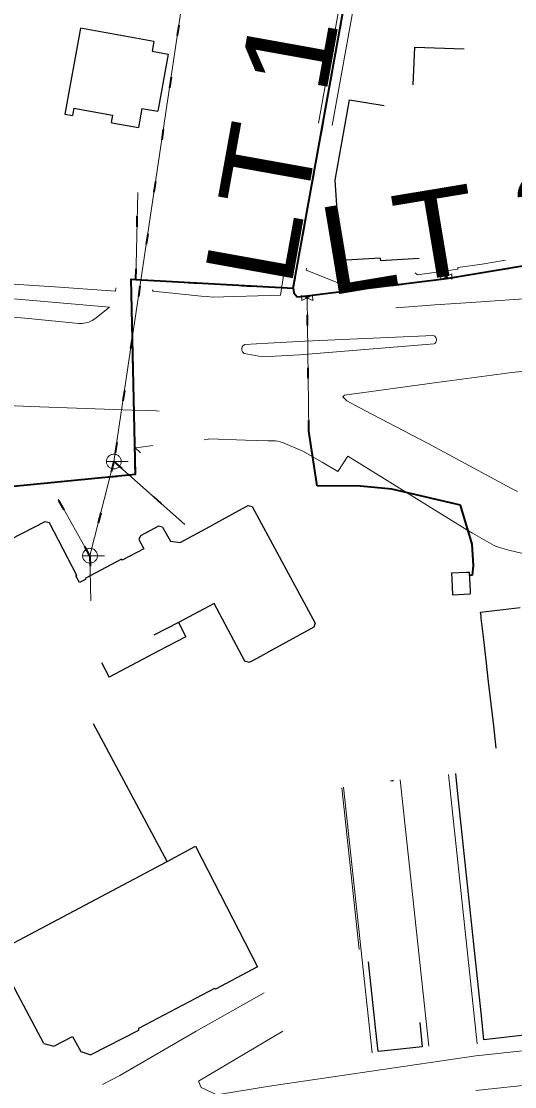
# Model space of a CAD drawing. Extents: x -968691 to -140888, y -1376050 to -879856.
# Drawn here: x -646308.7 to -646241.5, y -1062477.8 to -1062332.4 of the extents above; entities that cross this region are included whole.
import ezdxf
from ezdxf.enums import TextEntityAlignment as Align

# ---------------------------------------------------------------- set-up
doc = ezdxf.new("R2010")
doc.units = 0
doc.header["$LTSCALE"] = 4.8
for name, pattern in [('DASH_DOUBLE_DOT', [9.2, 5, -1.2, 0.3, -1.2, 0.3, -1.2]), ('DOTTED', [1.5, 0.3, -1.2]), ('LONG_DASHED', [7.5, 6, -1.5])]:
    doc.linetypes.add(name, pattern=pattern)
doc.layers.add('1', color=7, linetype='Continuous', lineweight=13)

msp = doc.modelspace()

# ---------------------------------------------------------------- linework, layer by layer
at = {"layer": '1'}
for p, q in [((-646262.19, -1062312.54), (-646268.225, -1062346.311)), ((-646260.32, -1062312.875), (-646266.355, -1062346.646)), ((-646286.21, -1062325.82), (-646296.122, -1062392.506)), ((-646293.117, -1062367.659), (-646292.87, -1062355.786)), ((-646273.428, -1062369.796), (-646272.751, -1062365.655)), ((-646269.896, -1062366.408), (-646269.848, -1062366.134)), ((-646265.209, -1062368.251), (-646269.896, -1062366.408)), ((-646254.709, -1062367.032), (-646255.046, -1062366.763)), ((-646249.248, -1062366.235), (-646254.709, -1062367.032)), ((-646312.371, -1062368.109), (-646303.55, -1062368.728)), ((-646312.411, -1062370.102), (-646308.696, -1062370.373)), ((-646303.55, -1062368.728), (-646295.911, -1062369.253)), ((-646290.786, -1062369.268), (-646284.212, -1062369.937)), ((-646282.733, -1062370.071), (-646273.428, -1062369.796)), ((-646269.774, -1062370.176), (-646269.801, -1062369.898)), ((-646308.696, -1062370.373), (-646296.712, -1062371.438)), ((-646298.709, -1062373.016), (-646296.712, -1062371.438)), ((-646269.53, -1062388.34), (-646269.774, -1062370.176)), ((-646247.414, -1062370.785), (-646238.073, -1062370.161)), ((-646314.855, -1062372.333), (-646307.745, -1062372.993)), ((-646307.745, -1062372.993), (-646300.902, -1062373.653)), ((-646270.09, -1062376.07), (-646252.56, -1062375.28)), ((-646278.29, -1062376.55), (-646275.09, -1062376.36)), ((-646275.09, -1062376.36), (-646270.09, -1062376.07)), ((-646252.47, -1062376.45), (-646270.75, -1062377.94)), ((-646275.86, -1062378.21), (-646278.34, -1062377.77)), ((-646270.75, -1062377.94), (-646275.86, -1062378.21)), ((-646252.076, -1062381.734), (-646264.679, -1062383.451)), ((-646306.24, -1062385.02), (-646319.42, -1062384.54)), ((-646264.679, -1062383.451), (-646264.927, -1062383.672)), ((-646293.624, -1062385.473), (-646306.24, -1062385.02)), ((-646289.937, -1062385.61), (-646290.37, -1062385.59)), ((-646261.889, -1062385.53), (-646253.371, -1062390.016)), ((-646268.43, -1062395.82), (-646269.53, -1062388.34)), ((-646283.208, -1062389.43), (-646283.83, -1062389.547)), ((-646275.105, -1062389.666), (-646278.162, -1062389.562)), ((-646253.371, -1062390.016), (-646241.928, -1062396.191)), ((-646265.578, -1062393.878), (-646264.212, -1062391.745)), ((-646250.506, -1062400.256), (-646264.212, -1062391.745)), ((-646296.122, -1062392.506), (-646299.377, -1062405.352)), ((-646297.13, -1062392.506), (-646294.153, -1062392.506)), ((-646296.122, -1062392.506), (-646286.466, -1062401.077)), ((-646262.49, -1062395.85), (-646268.43, -1062395.82)), ((-646258.22, -1062396.28), (-646262.49, -1062395.85)), ((-646248.85, -1062398.46), (-646258.22, -1062396.28)), ((-646299.377, -1062405.352), (-646303.731, -1062397.633)), ((-646247.27, -1062403.79), (-646248.85, -1062398.46)), ((-646300.385, -1062405.352), (-646297.408, -1062405.352)), ((-646299.377, -1062405.352), (-646299.27, -1062411.52)), ((-646247.22, -1062408.02), (-646247.686, -1062408.036)), ((-646250.514, -1062435.191), (-646246.61, -1062471.95)), ((-646260.895, -1062473.209), (-646264.803, -1062436.925)), ((-646253.194, -1062472.283), (-646257.089, -1062435.938)), ((-646265.055, -1062437.019), (-646262.682, -1062459.081)), ((-646275.652, -1062465.012), (-646284.904, -1062470.225)), ((-646191.32, -1062467.59), (-646246.76, -1062473.59)), ((-646284.904, -1062470.225), (-646295.307, -1062476.3)), ((-646273.072, -1062470.218), (-646284.6, -1062477.07)), ((-646246.8, -1062478.33), (-646190.49, -1062472.19)), ((-646246.76, -1062473.59), (-646275.206, -1062477.789)), ((-646295.307, -1062476.3), (-646297.658, -1062477.513))]:
    msp.add_line(p, q, dxfattribs=at)
at = {"layer": '1', "linetype": 'DOTTED', "lineweight": 40}
for p, q in [((-646271.669, -1062368.865), (-646261.793, -1062314.04)), ((-646286.21, -1062325.82), (-646296.122, -1062392.506)), ((-646293.117, -1062367.659), (-646292.87, -1062355.786)), ((-646269.774, -1062370.176), (-646269.801, -1062369.898)), ((-646269.53, -1062388.34), (-646269.774, -1062370.176)), ((-646296.122, -1062392.506), (-646299.377, -1062405.352)), ((-646296.122, -1062392.506), (-646286.466, -1062401.077)), ((-646299.377, -1062405.352), (-646303.731, -1062397.633)), ((-646299.377, -1062405.352), (-646299.27, -1062411.52))]:
    msp.add_line(p, q, dxfattribs=at)
at = {"layer": '1', "lineweight": 35}
msp.add_line((-646271.669, -1062368.865), (-646261.793, -1062314.04), dxfattribs=at)
at = {"layer": '1', "lineweight": 25}
for p, q in [((-646300.668, -1062333.382), (-646302.8, -1062345.11)), ((-646290.664, -1062335.183), (-646300.668, -1062333.382)), ((-646290.664, -1062335.183), (-646290.904, -1062336.501)), ((-646290.904, -1062336.501), (-646288.72, -1062336.898)), ((-646255.31, -1062341.076), (-646255.08, -1062335.946)), ((-646255.08, -1062335.946), (-646248.39, -1062336.189)), ((-646288.72, -1062336.898), (-646290.14, -1062344.71)), ((-646302.8, -1062345.11), (-646301.76, -1062345.29)), ((-646301.584, -1062344.273), (-646301.76, -1062345.29)), ((-646301.584, -1062344.273), (-646296.32, -1062345.23)), ((-646296.32, -1062345.23), (-646296.48, -1062346.25)), ((-646292.318, -1062344.321), (-646292.78, -1062346.91)), ((-646292.318, -1062344.321), (-646290.14, -1062344.71)), ((-646296.48, -1062346.25), (-646296.104, -1062346.317)), ((-646296.104, -1062346.317), (-646292.78, -1062346.91)), ((-646265.216, -1062365.085), (-646265.961, -1062354.088)), ((-646259.81, -1062364.763), (-646265.216, -1062365.085)), ((-646259.81, -1062364.763), (-646259.79, -1062365.101)), ((-646254.491, -1062364.785), (-646259.79, -1062365.101)), ((-646290.038, -1062401.322), (-646292.502, -1062402.641)), ((-646289.489, -1062401.472), (-646290.038, -1062401.322)), ((-646289.489, -1062401.472), (-646288.42, -1062403.36)), ((-646287.103, -1062403.549), (-646283.535, -1062401.619)), ((-646292.502, -1062402.641), (-646292.713, -1062403.154)), ((-646292.713, -1062403.154), (-646292.043, -1062404.413)), ((-646288.42, -1062403.36), (-646287.103, -1062403.549)), ((-646295.764, -1062406.193), (-646300.054, -1062408.469)), ((-646250.11, -1062407.7), (-646248.068, -1062407.598)), ((-646250.11, -1062407.7), (-646250.065, -1062408.613)), ((-646247.7, -1062407.58), (-646247.653, -1062408.529)), ((-646300.054, -1062408.469), (-646299.991, -1062408.577)), ((-646250.065, -1062408.613), (-646249.962, -1062410.677)), ((-646249.962, -1062410.677), (-646247.552, -1062410.557)), ((-646282.469, -1062411.878), (-646283.796, -1062412.579)), ((-646278.276, -1062419.745), (-646282.469, -1062411.878)), ((-646246.13, -1062413.04), (-646240.719, -1062412.421)), ((-646287.332, -1062414.447), (-646290.657, -1062416.203)), ((-646268.844, -1062415.08), (-646274.584, -1062418.247)), ((-646268.703, -1062414.534), (-646268.844, -1062415.08)), ((-646286.3, -1062416.401), (-646289.97, -1062418.339)), ((-646289.97, -1062418.339), (-646296.744, -1062421.917)), ((-646276.148, -1062419.084), (-646277.327, -1062419.734)), ((-646274.584, -1062418.247), (-646276.148, -1062419.084)), ((-646297.787, -1062419.911), (-646296.744, -1062421.917)), ((-646277.698, -1062419.932), (-646278.276, -1062419.745)), ((-646277.327, -1062419.734), (-646277.698, -1062419.932)), ((-646288.835, -1062447.069), (-646298.9, -1062428.31)), ((-646243.996, -1062431.595), (-646244.346, -1062428.587)), ((-646258.405, -1062436.074), (-646258.157, -1062436.044)), ((-646258.157, -1062436.044), (-646257.984, -1062436.035)), ((-646288.835, -1062447.069), (-646284.979, -1062444.987)), ((-646284.979, -1062444.987), (-646276.523, -1062461.442)), ((-646312.263, -1062459.5), (-646288.835, -1062447.069)), ((-646247.913, -1062450.241), (-646248.23, -1062447.251)), ((-646247.597, -1062453.223), (-646247.913, -1062450.241)), ((-646305.676, -1062471.913), (-646312.263, -1062459.5)), ((-646276.523, -1062461.442), (-646277.298, -1062461.859)), ((-646261.092, -1062463.758), (-646261.412, -1062460.769)), ((-646245.67, -1062471.4), (-646246.014, -1062468.156)), ((-646292.786, -1062470.128), (-646299.262, -1062473.467)), ((-646292.759, -1062469.884), (-646292.786, -1062470.128)), ((-646260.1, -1062473.01), (-646260.453, -1062469.719)), ((-646240.187, -1062470.76), (-646245.67, -1062471.4)), ((-646305.676, -1062471.913), (-646304.318, -1062472.289)), ((-646259.205, -1062472.915), (-646260.1, -1062473.01))]:
    msp.add_line(p, q, dxfattribs=at)
at = {"layer": '1', "linetype": 'LONG_DASHED', "lineweight": 40}
for p, q in [((-646268.43, -1062395.82), (-646269.53, -1062388.34)), ((-646262.49, -1062395.85), (-646268.43, -1062395.82)), ((-646258.22, -1062396.28), (-646262.49, -1062395.85)), ((-646248.85, -1062398.46), (-646258.22, -1062396.28)), ((-646247.27, -1062403.79), (-646248.85, -1062398.46)), ((-646247.22, -1062408.02), (-646247.686, -1062408.036))]:
    msp.add_line(p, q, dxfattribs=at)
at = {"layer": '1', "lineweight": 25}
for points in [[(-646265.961, -1062354.088), (-646263.992, -1062343.128), (-646259.268, -1062343.933)], [(-646283.535, -1062401.619), (-646280.91, -1062400.166), (-646279.068, -1062399.187), (-646277.8, -1062398.5)], [(-646277.8, -1062398.5), (-646277.26, -1062398.64), (-646268.703, -1062414.534)], [(-646301.156, -1062408.038), (-646304.911, -1062400.879), (-646305.538, -1062400.717), (-646310.227, -1062403.152)], [(-646292.043, -1062404.413), (-646294.995, -1062405.972), (-646295.077, -1062405.828), (-646295.764, -1062406.193)], [(-646248.068, -1062407.598), (-646247.757, -1062407.583), (-646247.7, -1062407.58)], [(-646299.991, -1062408.577), (-646300.794, -1062409.017), (-646301.293, -1062408.116), (-646301.156, -1062408.038)], [(-646247.653, -1062408.529), (-646247.574, -1062410.12), (-646247.552, -1062410.557)], [(-646283.796, -1062412.579), (-646287.332, -1062414.447), (-646286.3, -1062416.401)], [(-646246.034, -1062413.875), (-646246.069, -1062413.577), (-646246.13, -1062413.04)], [(-646244.346, -1062428.587), (-646244.695, -1062425.58), (-646245.045, -1062422.563), (-646245.391, -1062419.585), (-646245.749, -1062416.406), (-646246.034, -1062413.875)], [(-646248.23, -1062447.251), (-646248.546, -1062444.271), (-646248.864, -1062441.274), (-646249.18, -1062438.289), (-646249.52, -1062435.085)], [(-646246.014, -1062468.156), (-646246.33, -1062465.176), (-646246.646, -1062462.195), (-646246.962, -1062459.214), (-646247.278, -1062456.233), (-646247.597, -1062453.223)], [(-646277.298, -1062461.859), (-646282.274, -1062464.495), (-646282.402, -1062464.404), (-646292.759, -1062469.884)], [(-646260.453, -1062469.719), (-646260.772, -1062466.738), (-646261.092, -1062463.758)], [(-646254.41, -1062469.07), (-646254.09, -1062472.37), (-646259.205, -1062472.915)], [(-646304.318, -1062472.289), (-646301.752, -1062470.96), (-646300.608, -1062473.012), (-646299.262, -1062473.467)]]:
    msp.add_lwpolyline(points, dxfattribs=at)
at = {"layer": '1', "lineweight": 35}
for points in [[(-646250.776, -1062367.517), (-646227.54, -1062363.659), (-646208.022, -1062362.721), (-646205.775, -1062362.467)], [(-646332.93, -1062398.134), (-646293.189, -1062394.239), (-646293.768, -1062367.622), (-646293.117, -1062367.659), (-646271.669, -1062368.865)], [(-646269.801, -1062369.898), (-646265.454, -1062369.363), (-646250.776, -1062367.517)], [(-646271.669, -1062368.865), (-646271.578, -1062369.489), (-646271.129, -1062370.041), (-646269.801, -1062369.898)]]:
    msp.add_lwpolyline(points, dxfattribs=at)
at = {"layer": '1', "linetype": 'DOTTED', "lineweight": 40}
for points in [[(-646250.776, -1062367.517), (-646227.54, -1062363.659), (-646208.022, -1062362.721)], [(-646332.93, -1062398.134), (-646293.189, -1062394.239), (-646293.768, -1062367.622), (-646293.117, -1062367.659), (-646271.669, -1062368.865)], [(-646269.801, -1062369.898), (-646265.454, -1062369.363), (-646250.776, -1062367.517)], [(-646271.669, -1062368.865), (-646271.578, -1062369.489), (-646271.129, -1062370.041), (-646269.801, -1062369.898)]]:
    msp.add_lwpolyline(points, dxfattribs=at)
at = {"layer": '1'}
for points in [[(-646242.733, -1062365.022), (-646245.925, -1062365.58), (-646249.218, -1062366.027), (-646249.248, -1062366.235)], [(-646250.776, -1062367.517), (-646250.801, -1062367.289), (-646250.873, -1062366.381)], [(-646295.911, -1062369.253), (-646295.84, -1062368.868), (-646295.83, -1062368.815)], [(-646290.844, -1062369.064), (-646290.835, -1062369.097), (-646290.786, -1062369.268)], [(-646284.212, -1062369.937), (-646283.409, -1062369.999), (-646282.733, -1062370.071)], [(-646257.695, -1062371.54), (-646252.374, -1062371.121), (-646247.414, -1062370.785)], [(-646300.902, -1062373.653), (-646300.435, -1062373.658), (-646299.973, -1062373.595), (-646299.685, -1062373.52), (-646299.525, -1062373.465), (-646299.1, -1062373.271), (-646298.709, -1062373.016)], [(-646252.56, -1062375.28), (-646252.365, -1062375.395), (-646252.222, -1062375.571), (-646252.148, -1062375.785), (-646252.14, -1062375.9), (-646252.152, -1062376.012), (-646252.235, -1062376.223), (-646252.385, -1062376.393), (-646252.47, -1062376.45)], [(-646278.29, -1062376.55), (-646278.482, -1062376.682), (-646278.62, -1062376.87), (-646278.685, -1062377.094), (-646278.672, -1062377.327), (-646278.582, -1062377.542), (-646278.425, -1062377.714), (-646278.34, -1062377.77)], [(-646233.621, -1062379.553), (-646241.874, -1062380.373), (-646252.076, -1062381.734)], [(-646264.927, -1062383.672), (-646264.343, -1062384.202), (-646261.889, -1062385.53)], [(-646290.37, -1062385.59), (-646291.412, -1062385.553), (-646293.624, -1062385.473)], [(-646290.806, -1062390.296), (-646291.829, -1062390.451), (-646292.45, -1062390.524), (-646293.259, -1062390.594), (-646292.481, -1062391.309)], [(-646278.162, -1062389.562), (-646283.144, -1062389.421), (-646283.208, -1062389.43)], [(-646273.127, -1062389.887), (-646273.775, -1062389.729), (-646274.091, -1062389.683), (-646274.438, -1062389.655), (-646275.105, -1062389.666)], [(-646273.127, -1062389.887), (-646270.374, -1062391.098), (-646267.726, -1062392.575), (-646265.578, -1062393.878)], [(-646241.928, -1062396.191), (-646241.107, -1062396.57)], [(-646247.217, -1062402.289), (-646247.997, -1062401.807), (-646250.506, -1062400.256)], [(-646230.239, -1062404.022), (-646231.794, -1062404.592), (-646233.521, -1062405.049), (-646235.23, -1062405.317), (-646237.003, -1062405.44), (-646238.265, -1062405.382), (-646240.368, -1062405.066), (-646242.29, -1062404.608), (-646243.568, -1062404.224), (-646244.093, -1062404.057), (-646244.386, -1062403.896), (-646247.217, -1062402.289)], [(-646247.22, -1062408.02), (-646247.09, -1062406.75), (-646247.27, -1062403.79)], [(-646284.6, -1062477.07), (-646284.221, -1062477.926), (-646282.076, -1062478.919), (-646275.206, -1062477.789)]]:
    msp.add_lwpolyline(points, dxfattribs=at)
for points in [[(-646250.072, -1062366.896), (-646250.032, -1062367.595), (-646251.57, -1062366.983), (-646251.53, -1062367.682)], [(-646269.03, -1062369.813), (-646269.018, -1062370.513), (-646270.53, -1062369.839), (-646270.518, -1062370.539)], [(-646296.122, -1062391.498), (-646296.227, -1062391.504), (-646296.331, -1062391.52), (-646296.433, -1062391.547), (-646296.531, -1062391.585), (-646296.625, -1062391.633), (-646296.713, -1062391.69), (-646296.796, -1062391.757), (-646296.871, -1062391.832), (-646296.937, -1062391.914), (-646296.994, -1062392.001), (-646297.041, -1062392.096), (-646297.079, -1062392.195), (-646297.107, -1062392.296), (-646297.123, -1062392.401), (-646297.13, -1062392.506), (-646297.123, -1062392.611), (-646297.107, -1062392.716), (-646297.079, -1062392.818), (-646297.041, -1062392.916), (-646296.994, -1062393.009), (-646296.937, -1062393.099), (-646296.871, -1062393.181), (-646296.796, -1062393.255), (-646296.713, -1062393.321), (-646296.625, -1062393.379), (-646296.531, -1062393.427), (-646296.433, -1062393.465), (-646296.331, -1062393.492), (-646296.227, -1062393.508), (-646296.122, -1062393.514), (-646296.016, -1062393.508), (-646295.911, -1062393.492), (-646295.81, -1062393.465), (-646295.712, -1062393.427), (-646295.617, -1062393.379), (-646295.529, -1062393.321), (-646295.447, -1062393.255), (-646295.372, -1062393.181), (-646295.306, -1062393.099), (-646295.249, -1062393.009), (-646295.2, -1062392.916), (-646295.162, -1062392.818), (-646295.136, -1062392.716), (-646295.12, -1062392.611), (-646295.114, -1062392.506), (-646295.12, -1062392.401), (-646295.136, -1062392.296), (-646295.162, -1062392.195), (-646295.2, -1062392.096), (-646295.249, -1062392.001), (-646295.306, -1062391.914), (-646295.372, -1062391.832), (-646295.447, -1062391.757), (-646295.529, -1062391.69), (-646295.617, -1062391.633), (-646295.712, -1062391.585), (-646295.81, -1062391.547), (-646295.911, -1062391.52), (-646296.016, -1062391.504)], [(-646299.377, -1062404.344), (-646299.482, -1062404.35), (-646299.586, -1062404.366), (-646299.688, -1062404.393), (-646299.786, -1062404.431), (-646299.88, -1062404.479), (-646299.968, -1062404.536), (-646300.051, -1062404.603), (-646300.126, -1062404.678), (-646300.192, -1062404.76), (-646300.249, -1062404.847), (-646300.296, -1062404.942), (-646300.334, -1062405.041), (-646300.362, -1062405.142), (-646300.378, -1062405.247), (-646300.385, -1062405.352), (-646300.378, -1062405.457), (-646300.362, -1062405.562), (-646300.334, -1062405.664), (-646300.296, -1062405.762), (-646300.249, -1062405.855), (-646300.192, -1062405.945), (-646300.126, -1062406.027), (-646300.051, -1062406.101), (-646299.968, -1062406.167), (-646299.88, -1062406.225), (-646299.786, -1062406.273), (-646299.688, -1062406.311), (-646299.586, -1062406.338), (-646299.482, -1062406.354), (-646299.377, -1062406.36), (-646299.271, -1062406.354), (-646299.166, -1062406.338), (-646299.065, -1062406.311), (-646298.967, -1062406.273), (-646298.872, -1062406.225), (-646298.784, -1062406.167), (-646298.702, -1062406.101), (-646298.627, -1062406.027), (-646298.561, -1062405.945), (-646298.504, -1062405.855), (-646298.455, -1062405.762), (-646298.417, -1062405.664), (-646298.391, -1062405.562), (-646298.375, -1062405.457), (-646298.369, -1062405.352), (-646298.375, -1062405.247), (-646298.391, -1062405.142), (-646298.417, -1062405.041), (-646298.455, -1062404.942), (-646298.504, -1062404.847), (-646298.561, -1062404.76), (-646298.627, -1062404.678), (-646298.702, -1062404.603), (-646298.784, -1062404.536), (-646298.872, -1062404.479), (-646298.967, -1062404.431), (-646299.065, -1062404.393), (-646299.166, -1062404.366), (-646299.271, -1062404.35)]]:
    msp.add_lwpolyline(points, close=True, dxfattribs=at)
at = {"layer": '1', "linetype": 'DASH_DOUBLE_DOT', "lineweight": 40}
msp.add_lwpolyline([(-646250.776, -1062367.517), (-646250.801, -1062367.289), (-646250.873, -1062366.381)], dxfattribs=at)
at = {"layer": '1', "linetype": 'LONG_DASHED', "lineweight": 40}
msp.add_lwpolyline([(-646247.22, -1062408.02), (-646247.09, -1062406.75), (-646247.27, -1062403.79)], dxfattribs=at)
at = {"layer": '1'}
for centre in [(-646250.801, -1062367.289), (-646269.774, -1062370.176)]:
    msp.add_circle(centre, 0.132, dxfattribs=at)

# ---------------------------------------------------------------- texts
at = {"layer": '1', "width": 1.15}
for s, rotation, p in [('LT 150', 79.788, (-646266.9, -1062340.7)), ('LT 200', 9.427, (-646238.562, -1062365.185))]:
    msp.add_text(s, height=12, rotation=rotation, dxfattribs=at).set_placement(p, align=Align.CENTER)

doc.saveas('drawing.dxf')
